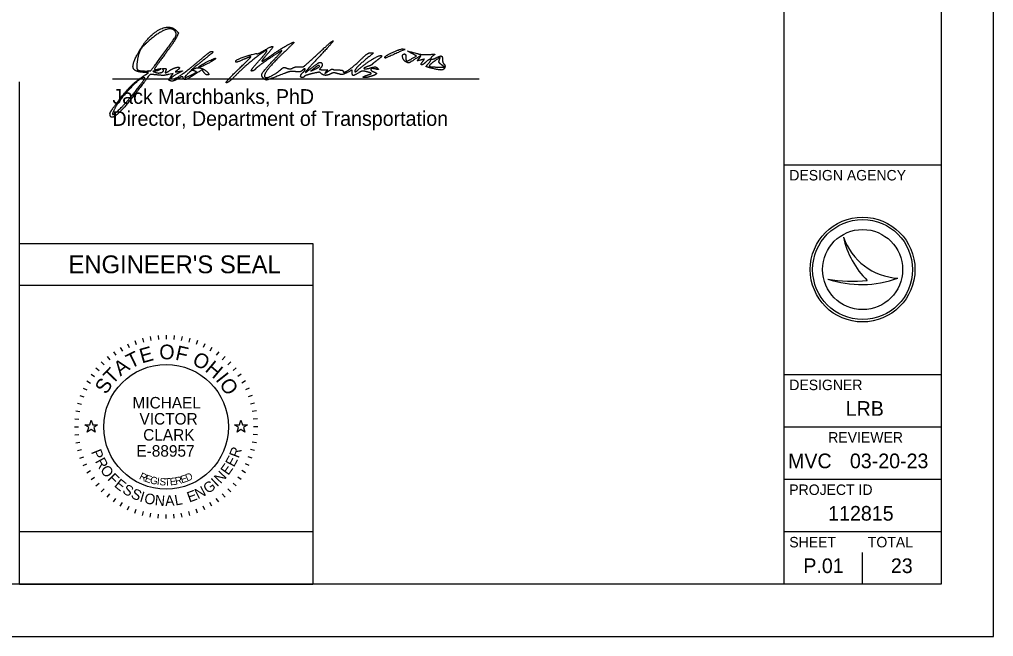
# Model space of a CAD drawing. Extents: x -14196 to 143, y -6096 to 28.
# Drawn here: x 24.7 to 34, y 0 to 5.89 of the extents above; entities that cross this region are included whole.
import ezdxf

# ---------------------------------------------------------------- set-up
doc = ezdxf.new("R2010")
doc.units = 0
for name, color, linetype in [('Default', 7, 'Continuous'), ('RS_Raster1', 7, 'Continuous'), ('SH_Border', 7, 'Continuous'), ('SH_Cut_Line', 7, 'Continuous'), ('SH_Data', 7, 'Continuous'), ('SH_Text', 7, 'Continuous')]:
    doc.layers.add(name, color=color, linetype=linetype)

msp = doc.modelspace()

# ---------------------------------------------------------------- linework, layer by layer
at = {"layer": 'Default'}
for points in [[(25.3236, 2.02), (25.3705, 2.02), (25.385, 2.0645), (25.3995, 2.02), (25.4464, 2.02), (25.4085, 1.9924), (25.423, 1.9478), (25.385, 1.9754), (25.347, 1.9478), (25.3615, 1.9924)], [(26.7536, 2.02), (26.8005, 2.02), (26.815, 2.0645), (26.8295, 2.02), (26.8764, 2.02), (26.8385, 1.9924), (26.853, 1.9478), (26.815, 1.9754), (26.777, 1.9478), (26.7915, 1.9924)]]:
    msp.add_lwpolyline(points, close=True, dxfattribs=at)
at = {"layer": 'RS_Raster1'}
msp.add_line((24.7, 0.5), (24.7, 5.2917), dxfattribs=at)
at = {"layer": 'SH_Border'}
for p, q in [((32, 0.5), (32, 21.5)), ((32, 4.5), (33.5, 4.5)), ((32, 2.5), (33.5, 2.5)), ((32, 2), (33.5, 2)), ((32, 1.5), (33.5, 1.5)), ((32, 1), (33.5, 1))]:
    msp.add_line(p, q, dxfattribs=at)
msp.add_lwpolyline([(1.5, 21.5), (33.5, 21.5), (33.5, 0.5), (1.5, 0.5)], close=True, dxfattribs=at)
at = {"layer": 'SH_Cut_Line'}
msp.add_lwpolyline([(0, 0), (34, 0), (34, 22), (0, 22)], close=True, dxfattribs=at)
at = {"layer": 'SH_Data'}
for p, q in [((25.5876, 5.3208), (29.0876, 5.3208)), ((24.7, 0.5), (24.7, 3.75)), ((24.7, 3.75), (27.5, 3.75)), ((27.5, 3.75), (27.5, 0.5)), ((32.5674, 3.8096), (32.5675, 3.8096)), ((32.75, 3.5), (32.75, 3.5)), ((24.7, 3.35), (27.5, 3.35)), ((32.4172, 3.4095), (32.4172, 3.4095)), ((33.0873, 3.4185), (33.0873, 3.4185)), ((25.7302, 2.793), (25.7471, 2.7568)), ((25.8007, 2.8222), (25.8144, 2.7846)), ((25.8735, 2.8452), (25.8839, 2.8065)), ((25.9481, 2.8617), (25.955, 2.8223)), ((26.0237, 2.8717), (26.0272, 2.8318)), ((26.1, 2.875), (26.1, 2.835)), ((26.1763, 2.8717), (26.1728, 2.8318)), ((26.2519, 2.8617), (26.245, 2.8223)), ((26.3265, 2.8452), (26.3161, 2.8065)), ((26.3993, 2.8222), (26.3856, 2.7846)), ((26.4698, 2.793), (26.4529, 2.7568)), ((25.5981, 2.7168), (25.6211, 2.684)), ((25.6625, 2.7578), (25.6825, 2.7231)), ((26.5375, 2.7578), (26.5175, 2.7231)), ((26.6019, 2.7168), (26.5789, 2.684)), ((25.4813, 2.6187), (25.5096, 2.5904)), ((25.5376, 2.6703), (25.5633, 2.6396)), ((26.6624, 2.6703), (26.6367, 2.6396)), ((26.7187, 2.6187), (26.6904, 2.5904)), ((25.4297, 2.5624), (25.4604, 2.5367)), ((26.7703, 2.5624), (26.7396, 2.5367)), ((25.3422, 2.4375), (25.3769, 2.4175)), ((25.3832, 2.5019), (25.416, 2.4789)), ((26.8168, 2.5019), (26.784, 2.4789)), ((26.8578, 2.4375), (26.8231, 2.4175)), ((25.307, 2.3698), (25.3432, 2.3529)), ((26.893, 2.3698), (26.8568, 2.3529)), ((25.2778, 2.2993), (25.3154, 2.2856)), ((26.9222, 2.2993), (26.8846, 2.2856)), ((25.2383, 2.1519), (25.2777, 2.145)), ((25.2548, 2.2265), (25.2935, 2.2161)), ((26.9452, 2.2265), (26.9065, 2.2161)), ((26.9617, 2.1519), (26.9223, 2.145)), ((25.2283, 2.0763), (25.2682, 2.0728)), ((26.9717, 2.0763), (26.9318, 2.0728)), ((25.225, 2), (25.265, 2)), ((26.975, 2), (26.935, 2)), ((25.2283, 1.9237), (25.2682, 1.9272)), ((26.9717, 1.9237), (26.9318, 1.9272)), ((25.2383, 1.8481), (25.2777, 1.855)), ((25.2548, 1.7735), (25.2935, 1.7839)), ((26.9452, 1.7735), (26.9065, 1.7839)), ((26.9617, 1.8481), (26.9223, 1.855)), ((25.2778, 1.7007), (25.3154, 1.7144)), ((26.9222, 1.7007), (26.8846, 1.7144)), ((25.307, 1.6302), (25.3432, 1.6471)), ((25.3422, 1.5625), (25.3769, 1.5825)), ((26.8578, 1.5625), (26.8231, 1.5825)), ((26.893, 1.6302), (26.8568, 1.6471)), ((25.3832, 1.4981), (25.416, 1.5211)), ((26.8168, 1.4981), (26.784, 1.5211)), ((25.4297, 1.4376), (25.4604, 1.4633)), ((25.4813, 1.3813), (25.5096, 1.4096)), ((26.7187, 1.3813), (26.6904, 1.4096)), ((26.7703, 1.4376), (26.7396, 1.4633)), ((25.5376, 1.3297), (25.5633, 1.3604)), ((25.5981, 1.2832), (25.6211, 1.316)), ((26.6019, 1.2832), (26.5789, 1.316)), ((26.6624, 1.3297), (26.6367, 1.3604)), ((25.6625, 1.2422), (25.6825, 1.2769)), ((25.7302, 1.207), (25.7471, 1.2432)), ((25.8007, 1.1778), (25.8144, 1.2154)), ((26.3993, 1.1778), (26.3856, 1.2154)), ((26.4698, 1.207), (26.4529, 1.2432)), ((26.5375, 1.2422), (26.5175, 1.2769)), ((25.8735, 1.1548), (25.8839, 1.1935)), ((25.9481, 1.1383), (25.955, 1.1777)), ((26.0237, 1.1283), (26.0272, 1.1682)), ((26.1, 1.125), (26.1, 1.165)), ((26.1763, 1.1283), (26.1728, 1.1682)), ((26.2519, 1.1383), (26.245, 1.1777)), ((26.3265, 1.1548), (26.3161, 1.1935)), ((32.75, 0.5), (32.75, 0.8)), ((32.375, 0.675), (32.375, 0.675)), ((24.7, 0.5), (27.5, 0.5))]:
    msp.add_line(p, q, dxfattribs=at)
msp.add_lwpolyline([(24.7, 0.5), (24.7, 1), (27.5, 1), (27.5, 0.5)], close=True, dxfattribs=at)
for centre, radius in [((32.75, 3.5), 0.5), ((32.75, 3.5), 0.4768), ((32.75, 3.5), 0.4768), ((32.75, 3.5), 0.3822), ((26.1, 2), 0.595)]:
    msp.add_circle(centre, radius, dxfattribs=at)
for centre, radius, start, end in [((33.1159, 3.9976), 0.5798, 198.92567, 198.93195), ((33.3467, 3.9701), 0.7956, 191.63793, 191.64215), ((33.1159, 3.9976), 0.5798, 198.93195, 267.16574), ((33.3467, 3.9701), 0.7956, 191.64215, 226.09467), ((32.7394, 4.37), 1.0131, 251.45764, 290.08324), ((32.648, 4.6543), 1.2661, 259.49639, 259.49952), ((32.7394, 4.37), 1.0131, 251.45274, 251.45764), ((32.648, 4.6543), 1.2661, 259.49952, 276.66723)]:
    msp.add_arc(centre, radius, start, end, dxfattribs=at)
at = {"layer": 'SH_Text'}
for p, q in [((26.0499, 5.5259), (26.0499, 5.5259)), ((28.1892, 5.525), (28.1892, 5.525)), ((26.3704, 5.3944), (26.3704, 5.3944)), ((26.4152, 5.436), (26.4152, 5.436)), ((26.787, 5.407), (26.787, 5.407)), ((27.5642, 5.438), (27.5642, 5.438)), ((28.6417, 5.4188), (28.6417, 5.4188))]:
    msp.add_line(p, q, dxfattribs=at)
for points in [[(28.453, 5.5155), (28.4894, 5.537), (28.4487, 5.5599)], [(27.5124, 5.4183), (27.4829, 5.3927), (27.5236, 5.4124)], [(28.7017, 5.4319), (28.7579, 5.432), (28.7292, 5.4541)], [(25.9022, 5.3589), (25.9329, 5.3802), (25.8951, 5.3808)], [(26.1452, 5.3391), (26.1664, 5.3714), (26.1247, 5.3614)]]:
    msp.add_lwpolyline(points, dxfattribs=at)
for points in [[(25.8386, 5.5767), (25.9248, 5.727), (26.133, 5.8431), (26.1986, 5.7774)], [(26.1897, 5.7682), (26.1637, 5.8102), (26.0376, 5.7691), (25.9422, 5.6874)], [(26.0499, 5.5259), (26.1712, 5.6893), (26.2037, 5.7455), (26.1897, 5.7682)], [(26.1986, 5.7774), (26.2174, 5.7586), (26.2174, 5.7536), (26.1991, 5.7152)], [(25.9422, 5.6874), (25.8756, 5.6304), (25.8368, 5.5663), (25.8257, 5.495)], [(26.1991, 5.7152), (26.1881, 5.6922), (26.1364, 5.6166), (26.0842, 5.5472)], [(27.5466, 5.5555), (27.6216, 5.6246), (27.6876, 5.6812), (27.6933, 5.6813)], [(27.6933, 5.6813), (27.6991, 5.6814), (27.647, 5.6212), (27.5777, 5.5476)], [(26.4287, 5.5031), (26.4792, 5.546), (26.5247, 5.5812), (26.5298, 5.5813)], [(26.5298, 5.5813), (26.5547, 5.5818), (26.5313, 5.5562), (26.4454, 5.489)], [(27.0614, 5.5884), (27.0518, 5.598), (26.8421, 5.4311), (26.7642, 5.3518)], [(27.2017, 5.5879), (27.1526, 5.5601), (26.9643, 5.4279), (26.9511, 5.412)], [(26.9677, 5.5594), (26.9733, 5.5576), (27.0028, 5.5707), (27.0333, 5.5886)], [(26.9836, 5.488), (27.0299, 5.5397), (27.0649, 5.5849), (27.0614, 5.5884)], [(27.0333, 5.5886), (27.1121, 5.6348), (27.1243, 5.6215), (27.0651, 5.5542)], [(27.0923, 5.5351), (27.1728, 5.5917), (27.3042, 5.669), (27.3199, 5.669)], [(27.1365, 5.509), (27.1827, 5.5582), (27.212, 5.5938), (27.2017, 5.5879)], [(27.3199, 5.669), (27.3248, 5.669), (27.2835, 5.6263), (27.2281, 5.5743)], [(28.1892, 5.525), (28.1892, 5.5374), (28.342, 5.6077), (28.3609, 5.6041)], [(28.3609, 5.6041), (28.3816, 5.6), (28.3823, 5.6004), (28.2607, 5.5458)], [(28.4487, 5.5599), (28.4058, 5.584), (28.4049, 5.5841), (28.5079, 5.5577)], [(25.8951, 5.3808), (25.7972, 5.3825), (25.7738, 5.4636), (25.8386, 5.5767)], [(25.8257, 5.495), (25.8143, 5.4217), (25.8357, 5.394), (25.9037, 5.394)], [(25.9037, 5.394), (25.9504, 5.394), (25.955, 5.3981), (26.0499, 5.5259)], [(26.0842, 5.5472), (26.0319, 5.4779), (25.9892, 5.4172), (25.9892, 5.4124)], [(26.1673, 5.319), (26.1904, 5.319), (26.3164, 5.4078), (26.4287, 5.5031)], [(26.4454, 5.489), (26.3522, 5.4159), (26.3308, 5.3944), (26.3747, 5.4179)], [(26.4152, 5.436), (26.4356, 5.4539), (26.5677, 5.5197), (26.5728, 5.5145)], [(26.5728, 5.5145), (26.579, 5.5083), (26.4364, 5.4315), (26.4187, 5.4315)], [(26.7644, 5.4908), (26.7646, 5.5014), (26.952, 5.5646), (26.9677, 5.5594)], [(26.8454, 5.5065), (26.7828, 5.4796), (26.7641, 5.476), (26.7644, 5.4908)], [(26.787, 5.407), (26.8581, 5.4755), (26.9134, 5.5315), (26.91, 5.5315)], [(26.91, 5.5315), (26.9065, 5.5315), (26.8775, 5.5202), (26.8454, 5.5065)], [(26.9178, 5.394), (26.9075, 5.394), (26.9364, 5.4352), (26.9836, 5.488)], [(27.0294, 5.3234), (27.0042, 5.3486), (27.0331, 5.3987), (27.1365, 5.509)], [(27.0651, 5.5542), (27.0371, 5.5224), (27.0142, 5.4927), (27.0142, 5.4883)], [(27.0142, 5.4883), (27.0142, 5.4838), (27.0493, 5.5049), (27.0923, 5.5351)], [(27.2281, 5.5743), (27.1284, 5.4805), (27.0392, 5.3724), (27.0392, 5.3454)], [(27.3716, 5.4331), (27.4051, 5.4303), (27.4285, 5.4467), (27.5466, 5.5555)], [(27.5777, 5.5476), (27.4482, 5.4101), (27.4161, 5.3628), (27.4983, 5.4306)], [(27.7892, 5.3925), (27.7892, 5.3696), (27.8845, 5.4311), (27.9548, 5.4993)], [(28.0267, 5.5215), (27.9527, 5.4606), (27.9017, 5.4071), (27.9017, 5.3903)], [(27.9361, 5.4081), (27.9897, 5.4569), (28.1366, 5.5469), (28.1535, 5.5413)], [(27.9548, 5.4993), (28, 5.5431), (28.0372, 5.5688), (28.0548, 5.5684)], [(28.0548, 5.5684), (28.0791, 5.5679), (28.0753, 5.5616), (28.0267, 5.5215)], [(28.1196, 5.4995), (28.0925, 5.4794), (28.0676, 5.4594), (28.0642, 5.4551)], [(28.1535, 5.5413), (28.1619, 5.5385), (28.1467, 5.5198), (28.1196, 5.4995)], [(28.2607, 5.5458), (28.1982, 5.5177), (28.1892, 5.5151), (28.1892, 5.525)], [(28.3902, 5.4809), (28.3637, 5.4951), (28.3527, 5.5565), (28.3767, 5.5565)], [(28.3767, 5.5565), (28.3836, 5.5565), (28.3892, 5.5424), (28.3892, 5.5252)], [(28.3892, 5.5252), (28.3892, 5.4884), (28.4035, 5.4862), (28.453, 5.5155)], [(28.4649, 5.4992), (28.4249, 5.4727), (28.4116, 5.4695), (28.3902, 5.4809)], [(28.5126, 5.5106), (28.537, 5.5402), (28.5212, 5.5365), (28.4649, 5.4992)], [(28.532, 5.4989), (28.4989, 5.4907), (28.4971, 5.4918), (28.5126, 5.5106)], [(28.5079, 5.5577), (28.5286, 5.5524), (28.5736, 5.5496), (28.6079, 5.5516)], [(28.5521, 5.4882), (28.5667, 5.5058), (28.5644, 5.507), (28.532, 5.4989)], [(28.5808, 5.4794), (28.5489, 5.4495), (28.5258, 5.4565), (28.5521, 5.4882)], [(28.606, 5.4668), (28.6364, 5.5005), (28.6148, 5.5114), (28.5808, 5.4794)], [(28.6079, 5.5516), (28.6628, 5.5546), (28.6677, 5.553), (28.6478, 5.5382)], [(28.6478, 5.5382), (28.619, 5.5167), (28.6419, 5.5004), (28.6756, 5.5184)], [(28.7094, 5.4997), (28.7193, 5.5254), (28.7111, 5.5224), (28.6485, 5.4768)], [(28.6756, 5.5184), (28.7158, 5.5399), (28.7392, 5.5342), (28.7392, 5.5027)], [(28.7292, 5.4541), (28.7088, 5.4698), (28.7031, 5.4831), (28.7094, 5.4997)], [(28.7392, 5.5027), (28.7392, 5.4869), (28.7456, 5.4676), (28.7533, 5.4598)], [(25.9892, 5.4124), (25.9892, 5.4077), (26.0047, 5.4073), (26.0236, 5.4117)], [(26.0392, 5.407), (26.0289, 5.4001), (26.0092, 5.3939), (25.9954, 5.3934)], [(25.9996, 5.3807), (26.0295, 5.3687), (26.0857, 5.3933), (26.0683, 5.4107)], [(26.0236, 5.4117), (26.0491, 5.4177), (26.0531, 5.4164), (26.0392, 5.407)], [(26.0683, 5.4107), (26.0637, 5.4152), (26.07, 5.419), (26.0822, 5.419)], [(26.0822, 5.419), (26.0968, 5.419), (26.1019, 5.4125), (26.0972, 5.4002)], [(26.0972, 5.4002), (26.0882, 5.377), (26.1011, 5.3763), (26.1333, 5.3983)], [(26.1333, 5.3983), (26.1622, 5.4181), (26.2267, 5.4356), (26.2267, 5.4237)], [(26.205, 5.3996), (26.1861, 5.3858), (26.1881, 5.3845), (26.2207, 5.3895)], [(26.2267, 5.4237), (26.2267, 5.4192), (26.2169, 5.4084), (26.205, 5.3996)], [(26.2207, 5.3895), (26.2575, 5.395), (26.2573, 5.3948), (26.2119, 5.3696)], [(26.3704, 5.3944), (26.3532, 5.4007), (26.3367, 5.3956), (26.3173, 5.3778)], [(26.3423, 5.3581), (26.3887, 5.3817), (26.3923, 5.3863), (26.3704, 5.3944)], [(26.3747, 5.4179), (26.3873, 5.4246), (26.4112, 5.4267), (26.4278, 5.4225)], [(26.4608, 5.3811), (26.444, 5.4052), (26.4419, 5.4048), (26.3762, 5.3624)], [(26.4187, 5.4315), (26.4139, 5.4315), (26.4124, 5.4335), (26.4152, 5.436)], [(26.4278, 5.4225), (26.4639, 5.4134), (26.5223, 5.3565), (26.4955, 5.3565)], [(26.6767, 5.2822), (26.6664, 5.2824), (26.716, 5.3385), (26.787, 5.407)], [(26.9511, 5.412), (26.9428, 5.4021), (26.9279, 5.394), (26.9178, 5.394)], [(27.0572, 5.3315), (27.079, 5.3315), (27.1603, 5.3767), (27.1967, 5.409)], [(27.1967, 5.409), (27.217, 5.427), (27.2299, 5.4296), (27.2536, 5.4206)], [(27.2536, 5.4206), (27.2738, 5.4129), (27.2926, 5.4136), (27.3086, 5.4227)], [(27.3086, 5.4227), (27.322, 5.4302), (27.3503, 5.4349), (27.3716, 5.4331)], [(27.4041, 5.4024), (27.3884, 5.3882), (27.3672, 5.3838), (27.3346, 5.388)], [(27.4267, 5.4099), (27.4267, 5.417), (27.4165, 5.4136), (27.4041, 5.4024)], [(27.4079, 5.3815), (27.4182, 5.39), (27.4267, 5.4028), (27.4267, 5.4099)], [(27.4983, 5.4306), (27.5467, 5.4705), (27.5892, 5.4808), (27.5892, 5.4527)], [(27.5642, 5.438), (27.5642, 5.4515), (27.5401, 5.4423), (27.5124, 5.4183)], [(27.5236, 5.4124), (27.5459, 5.4232), (27.5642, 5.4348), (27.5642, 5.438)], [(27.5742, 5.4215), (27.5625, 5.4098), (27.5684, 5.4065), (27.6007, 5.4065)], [(27.5892, 5.4527), (27.5892, 5.4438), (27.5824, 5.4297), (27.5742, 5.4215)], [(27.6007, 5.4065), (27.6383, 5.4065), (27.6406, 5.4044), (27.6251, 5.3851)], [(27.6468, 5.391), (27.6682, 5.406), (27.689, 5.415), (27.6929, 5.4111)], [(27.6929, 5.4111), (27.6968, 5.4072), (27.7201, 5.404), (27.7446, 5.404)], [(27.7446, 5.404), (27.7691, 5.404), (27.7892, 5.3988), (27.7892, 5.3925)], [(27.8767, 5.3799), (27.8767, 5.4028), (27.8756, 5.4028), (27.8295, 5.38)], [(27.9017, 5.3903), (27.9017, 5.3829), (27.9172, 5.3909), (27.9361, 5.4081)], [(28.0218, 5.3849), (27.983, 5.3948), (27.9662, 5.3932), (27.9386, 5.3769)], [(28.0298, 5.4386), (27.9803, 5.4231), (27.9998, 5.4094), (28.0516, 5.4233)], [(28.0642, 5.4551), (28.0607, 5.4508), (28.0453, 5.4434), (28.0298, 5.4386)], [(28.0516, 5.4233), (28.09, 5.4335), (28.1052, 5.4329), (28.1172, 5.4206)], [(28.0986, 5.4132), (28.0618, 5.4223), (28.0486, 5.3992), (28.0829, 5.386)], [(28.1172, 5.4206), (28.1299, 5.4078), (28.1263, 5.4063), (28.0986, 5.4132)], [(28.6417, 5.4188), (28.5869, 5.4318), (28.5812, 5.4394), (28.606, 5.4668)], [(28.6485, 5.4768), (28.6058, 5.4457), (28.6223, 5.4318), (28.7017, 5.4319)], [(28.76, 5.4261), (28.7519, 5.405), (28.7107, 5.4024), (28.6417, 5.4188)], [(28.7533, 5.4598), (28.7611, 5.452), (28.7641, 5.4368), (28.76, 5.4261)], [(25.8951, 5.3297), (25.8742, 5.3506), (25.6557, 5.1249), (25.6094, 5.0346)], [(25.6513, 5.1167), (25.7289, 5.2172), (25.809, 5.2945), (25.9022, 5.3589)], [(25.6795, 5.0533), (25.7471, 5.1224), (25.9028, 5.322), (25.8951, 5.3297)], [(25.9835, 5.359), (25.95, 5.3624), (25.9383, 5.3519), (25.8617, 5.2502)], [(25.9954, 5.3934), (25.973, 5.3925), (25.9735, 5.3912), (25.9996, 5.3807)], [(26.1247, 5.3614), (26.0843, 5.3516), (26.062, 5.3512), (25.9835, 5.359)], [(26.144, 5.299), (26.1258, 5.306), (26.1259, 5.3097), (26.1452, 5.3391)], [(26.2106, 5.3189), (26.1849, 5.3037), (26.155, 5.2948), (26.144, 5.299)], [(26.2119, 5.3696), (26.1608, 5.3414), (26.1411, 5.319), (26.1673, 5.319)], [(26.2617, 5.3327), (26.2589, 5.3412), (26.2396, 5.336), (26.2106, 5.3189)], [(26.3762, 5.3624), (26.3073, 5.318), (26.2698, 5.3083), (26.2617, 5.3327)], [(26.3173, 5.3778), (26.2731, 5.3374), (26.2843, 5.3285), (26.3423, 5.3581)], [(26.4955, 5.3565), (26.4859, 5.3565), (26.4703, 5.3676), (26.4608, 5.3811)], [(26.7642, 5.3518), (26.7264, 5.3133), (26.687, 5.282), (26.6767, 5.2822)], [(27.229, 5.3709), (27.083, 5.3132), (27.048, 5.3048), (27.0294, 5.3234)], [(27.0392, 5.3454), (27.0392, 5.3377), (27.0473, 5.3315), (27.0572, 5.3315)], [(27.3346, 5.388), (27.3054, 5.3917), (27.2655, 5.3853), (27.229, 5.3709)], [(27.4009, 5.3315), (27.3826, 5.3315), (27.3871, 5.3642), (27.4079, 5.3815)], [(27.4191, 5.3418), (27.4156, 5.3361), (27.4074, 5.3315), (27.4009, 5.3315)], [(27.4953, 5.3689), (27.4569, 5.3597), (27.4226, 5.3475), (27.4191, 5.3418)], [(27.5796, 5.3711), (27.5685, 5.3822), (27.5484, 5.3817), (27.4953, 5.3689)], [(27.6759, 5.3685), (27.6452, 5.3521), (27.5973, 5.3533), (27.5796, 5.3711)], [(27.6251, 5.3851), (27.6131, 5.3701), (27.6196, 5.3718), (27.6468, 5.391)], [(27.7404, 5.3686), (27.7135, 5.3763), (27.6904, 5.3763), (27.6759, 5.3685)], [(27.8295, 5.38), (27.7921, 5.3615), (27.7735, 5.3591), (27.7404, 5.3686)], [(27.9386, 5.3769), (27.8936, 5.3503), (27.8767, 5.3511), (27.8767, 5.3799)], [(28.0578, 5.3439), (28.0112, 5.3285), (27.9639, 5.3343), (28.0079, 5.35)], [(28.0079, 5.35), (28.0217, 5.3549), (28.0414, 5.3619), (28.0517, 5.3657)], [(28.0517, 5.3657), (28.0631, 5.3698), (28.0514, 5.3774), (28.0218, 5.3849)], [(28.0829, 5.386), (28.1135, 5.3743), (28.1046, 5.3594), (28.0578, 5.3439)], [(25.8617, 5.2502), (25.7093, 5.0481), (25.5642, 4.9195), (25.5642, 4.9865)], [(25.5642, 4.9865), (25.5642, 4.9961), (25.6034, 5.0547), (25.6513, 5.1167)], [(25.6094, 5.0346), (25.5781, 4.9736), (25.6098, 4.9821), (25.6795, 5.0533)]]:
    msp.add_open_spline(points, degree=2, dxfattribs=at)

# ---------------------------------------------------------------- texts
at = {"layer": 'SH_Data'}
for s, height, p in [('DESIGN AGENCY', 0.1, (32.05, 4.35)), ("ENGINEER'S SEAL", 0.17, (25.1676, 3.465)), ('DESIGNER', 0.1, (32.05, 2.35)), ('MICHAEL', 0.11, (25.7789, 2.1749)), ('LRB', 0.14, (32.5886, 2.105)), ('VICTOR', 0.11, (25.8457, 2.0216)), ('CLARK', 0.11, (25.881, 1.8684)), ('REVIEWER', 0.1, (32.4218, 1.85)), ('E-88957', 0.11, (25.8159, 1.7151)), ('MVC', 0.14, (32.0383, 1.605)), ('03-20-23', 0.14, (32.6289, 1.605)), ('PROJECT ID', 0.1, (32.05, 1.35)), ('112815', 0.14, (32.4212, 1.105)), ('SHEET', 0.1, (32.05, 0.85)), ('TOTAL', 0.1, (32.8, 0.85)), ('P.01', 0.14, (32.1844, 0.605)), ('23', 0.14, (33.02, 0.605))]:
    msp.add_text(s, height=height, dxfattribs=at).set_placement(p)
for s, height, rotation, p in [('T', 0.14, 25.71674, (25.7616, 2.5518)), ('E', 0.14, 15.75706, (25.8684, 2.6038)), ('O', 0.14, 359.78119, (26.0347, 2.6443)), ('F', 0.14, 347.43619, (26.1811, 2.6417)), ('O', 0.14, 332.25863, (26.3398, 2.6015)), ('A', 0.14, 36.47472, (25.6634, 2.4781)), ('H', 0.14, 319.91363, (26.4632, 2.5361)), ('T', 0.14, 46.4344, (25.5883, 2.3964)), ('I', 0.14, 308.36695, (26.5665, 2.4483)), ('S', 0.14, 57.19238, (25.5281, 2.3014)), ('O', 0.14, 303.14906, (26.6021, 2.4089)), ('P', 0.1, 291.49398, (25.3823, 1.7621)), ('R', 0.1, 69.23216, (26.7919, 1.6954)), ('R', 0.1, 298.73106, (25.419, 1.6717)), ('E', 0.1, 61.99508, (26.7476, 1.6098)), ('O', 0.1, 306.46664, (25.4655, 1.5883)), ('N', 0.1, 47.02243, (26.6202, 1.4508)), ('E', 0.1, 54.75801, (26.6933, 1.5314)), ('F', 0.1, 314.7068, (25.5343, 1.4983)), ('E', 0.1, 321.43929, (25.5978, 1.4348)), ('R', 0.07, 334.48695, (25.8375, 1.5051)), ('E', 0.07, 341.03996, (25.8906, 1.4801)), ('G', 0.07, 347.47515, (25.9414, 1.4618)), ('I', 0.07, 353.78581, (26.0091, 1.4468)), ('S', 0.07, 356.89262, (26.0358, 1.4429)), ('T', 0.07, 3.00609, (26.0857, 1.4387)), ('E', 0.07, 6.01169, (26.1389, 1.4412)), ('R', 0.07, 11.91844, (26.1925, 1.4474)), ('E', 0.07, 17.68363, (26.2498, 1.4602)), ('D', 0.07, 23.30524, (26.301, 1.477)), ('I', 0.1, 43.28703, (26.5868, 1.4214)), ('S', 0.1, 328.67637, (25.6743, 1.3752)), ('S', 0.1, 335.91345, (25.7564, 1.3266)), ('E', 0.1, 20.07421, (26.3212, 1.277)), ('N', 0.1, 27.31129, (26.4045, 1.3075)), ('G', 0.1, 35.04687, (26.4981, 1.357)), ('I', 0.1, 343.15053, (25.8406, 1.2897)), ('O', 0.1, 346.88592, (25.8839, 1.2751)), ('N', 0.1, 355.12608, (25.9888, 1.2517)), ('A', 0.1, 2.86166, (26.0923, 1.2437)), ('L', 0.1, 10.09874, (26.1894, 1.249))]:
    msp.add_text(s, height=height, rotation=rotation, dxfattribs=at).set_placement(p)
at = {"layer": 'SH_Text'}
for s, p in [('Jack Marchbanks, PhD', (25.5876, 5.0808)), ('Director, Department of Transportation', (25.5876, 4.8708))]:
    msp.add_text(s, height=0.14, dxfattribs=at).set_placement(p)

doc.saveas('drawing.dxf')
